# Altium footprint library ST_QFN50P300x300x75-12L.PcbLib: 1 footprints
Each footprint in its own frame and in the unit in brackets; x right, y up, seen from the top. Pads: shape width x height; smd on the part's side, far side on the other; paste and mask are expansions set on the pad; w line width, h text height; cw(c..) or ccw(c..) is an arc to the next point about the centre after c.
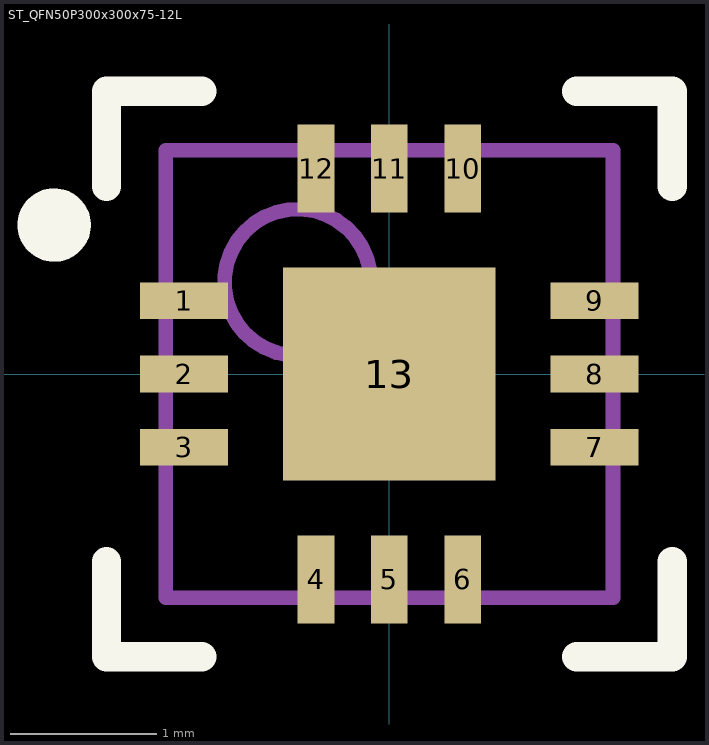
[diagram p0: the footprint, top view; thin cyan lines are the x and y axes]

## ST_QFN50P300x300x75-12L [mm]
height 1
pads (13):
  rect 0.6x0.25 smd: 1(-1.4,0.5) 2(-1.4,0) 3(-1.4,-0.5) 7(1.4,-0.5) 8(1.4,0) 9(1.4,0.5)
  rect 0.25x0.6 smd: 4(-0.5,-1.4) 5(0,-1.4) 6(0.5,-1.4) 10(0.5,1.4) 11(0,1.4) 12(-0.5,1.4)
  rect 1.45x1.45 smd: 13(0,0)
Top Overlay:
  circle w0.25: c-2.286,1.016 r0.125
  lines w0.2: -1.929,-1.279 -1.929,-1.929 -1.279,-1.929 ; -1.929,1.279 -1.929,1.929 -1.279,1.929 ; 1.279,-1.929 1.929,-1.929 1.929,-1.279 ; 1.279,1.929 1.929,1.929 1.929,1.279
Mechanical 13:
  circle w0.1: c-0.625,0.625 r0.5
  lines w0.1: -1.525,-1.525 -1.525,1.525 1.525,1.525 1.525,-1.525 -1.525,-1.525
3D body "ST_QFN50P300x300x75-12L.step": height 1, standoff 0, extent -1.526,-1.526 1.526,1.526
